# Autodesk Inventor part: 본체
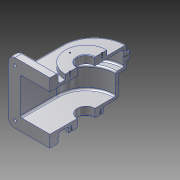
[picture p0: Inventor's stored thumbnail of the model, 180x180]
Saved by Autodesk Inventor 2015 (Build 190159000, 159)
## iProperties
Created: 2017-11
Part Number: 본체
Material: 알루미늄 6061
Document SubType Name: Modeling
Designer: 2-PC06
Density: 2.7 g/cm^3
Appearance: 알루미늄 - 평지
Mass: 1004.1 g
Surface Area: 1222.61 cm^2
Volume: 371.888 cm^3
Author: 2-PC06
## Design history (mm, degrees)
sketch "스케치1"
  geometry: L1 (-75, 55)-(75, 55); L2 (75, 55)-(75, -55); L3 (75, -55)-(-75, -55); L4 (-75, -55)-(-75, 55); L5 (-75, 55)-(75, -55); L6 (75, 55)-(-75, -55); 1 further point
  constraints: 12 end point, 2 midpoint, 2 parallel, 1 horizontal, 1 perpendicular
  dimensions: "d0" = 110 distance of L1.end L2.end; "d1" = 150 distance of L2.end L3.end
extrude "돌출1" new body sketch "스케치1" distance "d2" = 15; taper "d3" = 0 deg
sketch "스케치2"
  geometry: L1 (75, 0)-(-75, 0) reference; L2 (0, 80)-(0, 0); L3 (-58, 80)-(-58, 15); L4 (-75, 15)-(75, 15) reference; L5 (58, 80)-(58, 15); A1 r 58 centre (0, 80) between (58, 80) and (-58, 80)
  constraints: 6 end point, 2 perpendicular, 2 point on circle, 2 point on line, 2 tangent, 1 centre point, 1 vertical
  dimensions: "d4" = 116 diameter of A1; "d5" = 80 distance from line of L1 L2.start
extrude "돌출2" join sketch "스케치2" distance "d7" = 38; taper "d8" = 0 deg
sketch "스케치3"
  geometry: L1 (75, 0)-(-75, 0) reference; L2 (0, 65)-(0, 0); L3 (58, 80)-(58, 15) reference; L4 (58, 65)-(58, 15); L5 (58, 15)-(-58, 15); L6 (-75, 15)-(75, 15) reference; L7 (-58, 15)-(-58, 65); L8 (-58, 15)-(-58, 80) reference; A1 r 58 centre (0, 65) between (58, 65) and (-58, 65)
  constraints: 8 end point, 2 collinear, 2 point on circle, 2 point on line, 1 centre point, 1 perpendicular
  dimensions: "d10" = 65 distance from line of L1 L2.start; "d11" = 58 radius of A1
extrude "돌출3" join sketch "스케치3" distance "d12" = 38; taper "d13" = 0 deg
sketch "스케치4"
  geometry: C1 r 31 at (0, 65); A1 r 58 centre (0, 65) between (58, 65) and (-58, 65) reference; 1 further point
  constraints: 1 centre point, 1 concentric
  dimensions: "d14" = 62 diameter of C1
extrude "돌출4" join sketch "스케치4" distance "d15" = 10; taper "d16" = 0 deg
sketch "스케치5"
  geometry: C1 r 37.5 at (0, 65); C2 r 31 at (0, 65) reference; 1 further point
  constraints: 1 centre point, 1 concentric
  dimensions: "d17" = 75 diameter of C1
extrude "돌출5" join sketch "스케치5" distance "d18" = 9; taper "d19" = 0 deg
feature "쉘1" dims "d23" = 5
sketch "스케치7"
  geometry: C1 r 16 at (0, 0); C2 r 37.5 at (0, 0) reference; 1 further point
  constraints: 1 centre point, 1 concentric
  dimensions: "d24" = 32 diameter of C1
extrude "돌출7" cut sketch "스케치7" stored distance "d25" = 15; taper "d26" = 0 deg
sketch "스케치8"
  geometry: L1 (17, -83)-(123, -83); L2 (123, -83)-(123, -17); L3 (123, -17)-(17, -17); L4 (17, -17)-(17, -83); L5 (17, -83)-(123, -17); L6 (123, -83)-(17, -17); L7 (0, -100)-(140, -100); L8 (140, -100)-(140, 0); L9 (140, 0)-(0, 0); L10 (0, 0)-(0, -100); L11 (0, -100)-(140, 0); L12 (140, -100)-(0, 0); 1 further point
  constraints: 24 end point, 4 midpoint, 4 parallel, 2 horizontal, 2 perpendicular
extrude "돌출8" join sketch "스케치8" distance "d27" = 10; taper "d28" = 0 deg
fillet "모깎기1" dims "d29" = 12
node "작업 평면1"
sketch "스케치9"
  geometry: L1 (-75, -43)-(-75, 43) reference; L2 (58, 38)-(-58, 38) reference; C1 r 6 at (0, 19); 1 further point
  constraints: 1 centre point
  dimensions: "d31" = 12 diameter of C1; "d32" = 75 distance from line of L1 C1.centre; "d33" = 19 distance from line of L2 C1.centre
extrude "돌출9" join sketch "스케치9" stored distance "d34" = 15; taper "d35" = 0 deg
sketch "스케치10"
  geometry: C1 r 6 at (-63, -43); A1 r 12 centre (-63, -43) between (-75, -43) and (-63, -55) reference; 1 further point
  constraints: 1 centre point, 1 concentric
  dimensions: "d36" = 12 diameter of C1
extrude "돌출10" cut sketch "스케치10" distance "d37" = 5; taper "d38" = 0 deg
sketch "스케치11"
  geometry: C1 r 2.5 at (0, 0); C2 r 6 at (0, 0) reference; 1 further point
  constraints: 1 centre point, 1 concentric
  dimensions: "d39" = 5 diameter of C1
extrude "돌출11" cut sketch "스케치11" stored distance "d40" = 5; taper "d41" = 0 deg
fillet "모깎기2" dims "d42" = 3
chamfer "모따기1" distance "d43" = 1; stored, may be unused: second distance "d44" = 2, angle "d45" = 45 deg
fillet "모깎기3" dims "d46" = 3
fillet "모깎기4" dims "d47" = 3
sketch "스케치16"
  geometry: C1 r 16 at (0, 0) reference; C2 r 32.5 at (0, 0) reference; 1 further point
extrude "돌출12" join sketch "스케치16" stored distance "d82" = 5; taper "d83" = 0 deg
sketch "스케치12"
  geometry: L1 (0, 29)-(0, 0); C1 r 26 at (0, 0) reference; 1 further point
  constraints: 2 end point, 1 vertical
  dimensions: "d48" = 29 distance of L1.start L1.end
hole "구멍1" sketch "스케치12" at (0, 29) diameter "d49" = 2.459; stored, may be unused: countersink angle "d53" = 90 deg, drill point angle "d55" = 118 deg; dims "d50" = 6, "d51" = 12, "d52" = 5, "d54" = 8.8
sketch "스케치13" dims "d59" = 52
  geometry: C1 r 31 at (0, 0) reference; 3 further points
  constraints: 2 vertical alignment, 3 other
hole "구멍2" sketch "스케치13" at (0, 26) diameter "d60" = 2.459; stored, may be unused: countersink angle "d64" = 90 deg, drill point angle "d66" = 118 deg; dims "d61" = 6, "d62" = 12, "d63" = 5, "d65" = 8.8
sketch "스케치17"
  geometry: C1 r 16 at (0, -26) reference; C2 r 26 at (0, -26) reference; 1 further point
extrude "돌출13" join sketch "스케치17" stored distance "d84" = 5; taper "d85" = 0 deg
sketch "스케치14"
  geometry: L1 (6, 0)-(-6, 0); L2 (0, -6)-(0, 6); A1 r 6 centre (0, 0) between (6, 0) and (-6, 0) reference; 2 further points
  constraints: 4 end point, 4 point on circle, 1 coincident, 1 horizontal, 1 vertical
hole "구멍3" sketch "스케치14" at (0, 0) diameter "d70" = 4.134; stored, may be unused: countersink angle "d74" = 90 deg, drill point angle "d76" = 118 deg; dims "d71" = 10, "d72" = 12, "d73" = 5, "d75" = 14.2
sketch "스케치15"
  geometry: L1 (-24.246, -15.885)-(30.246, -15.885); L2 (30.246, -15.885)-(30.246, -34.115); L3 (30.246, -34.115)-(-24.246, -34.115); L4 (-24.246, -34.115)-(-24.246, -15.885); L5 (-24.246, -25)-(30.246, -25); L6 (3, -15.885)-(3, -34.115); L7 (-35, 15)-(-35, -47) reference; L8 (46, -65)-(-40, -65) reference; 1 further point
  constraints: 4 end point, 4 midpoint, 2 other
  dimensions: "d77" = 38 distance between parallel lines of L7 L6; "d78" = 40 distance between parallel lines of L8 L5
feature "엠보싱1" sketch "스케치15" dims "d79" = 0.5, "d80" = 0
fillet "모깎기5" dims "d81" = 3
node "솔리드1"
mirror "대칭1"
mirror "대칭2"
mirror "대칭3"
mirror "대칭4"
pattern_circular "원형 패턴1" dims angle "d57" = 360 deg
pattern_circular "원형 패턴2" dims angle "d68" = 360 deg
other parameters: "d6" = 38, "d9" = 116, "d30" = -144
